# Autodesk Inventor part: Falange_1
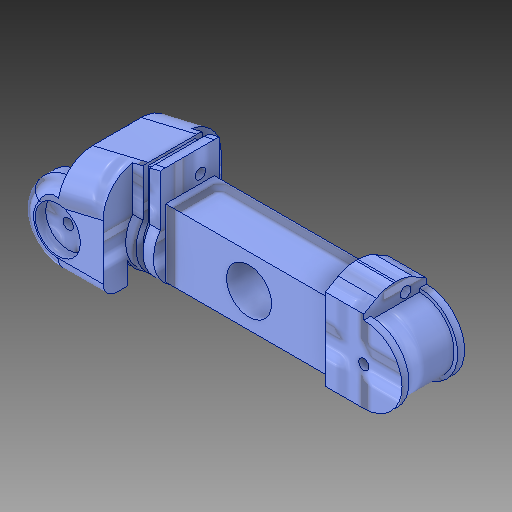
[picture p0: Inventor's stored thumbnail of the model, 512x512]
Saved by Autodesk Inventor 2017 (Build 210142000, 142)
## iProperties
Created: 2017-02
Part Number: Falange_1
Material: Generic
Document SubType Name: Modeling
Designer: alez_
Density: 1 g/cm^3
Appearance: 4in Square - Light Blue
Author: alez_
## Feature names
1. Extrusion1
2. Extrusion2
3. Extrusion3
4. Extrusion4
5. Extrusion5
6. Extrusion6
7. Extrusion7
8. Extrusion8
9. Sweep1
10. Sweep2
11. Fillet1
12. Fillet2
13. Extrusion9
14. Extrusion10
15. Extrusion11
16. Extrusion12
17. Extrusion13
18. Fillet3
19. Fillet4
20. Extrusion14
21. Extrusion16
22. Extrusion17
23. Extrusion18
24. Extrusion19
25. Extrusion20
26. Extrusion21
27. Extrusion22
28. Extrusion23
29. Extrusion24
30. Fillet5
31. Extrusion25
32. Extrusion26
## Parameters: d0 = 18 mm, d1 = 17 mm, d2 = 16 mm, d3 = 0, d4 = 8.5 mm, d6 = 4.25 mm, d7 = 8.5 mm, d8 = 4 mm, d9 = 0, d17 = 17 mm, d18 = 0, d19 = 13.5 mm, d20 = 17 mm, d21 = 0, d22 = 6.5 mm, d23 = 1.5 mm, d24 = 0, d25 = 1.5 mm, d26 = 0, d27 = 1.5 mm, d28 = 14 mm, d29 = 0, d30 = 5 mm, d33 = 8 mm, d34 = 0, d35 = 1.5 mm, d36 = 0, d37 = 0, d38 = 1.5 mm, d39 = 0, d40 = 0, d41 = 5 mm, d42 = 5 mm, d44 = 0, d45 = 11 mm, d47 = 0, d49 = 1 mm, d50 = 1 mm, d51 = 0.75 mm, d52 = 11 mm, d55 = 0, d56 = 10.5 mm, d57 = 1 mm, d58 = 0, d59 = 2 mm, d60 = 0, d61 = 1 mm, d62 = 2 mm, d63 = 15 mm, d64 = 3.25 mm, d65 = 0, d76 = -1.5 mm, d77 = 1 mm, d78 = 1 mm, d79 = 0, d85 = 13.5 mm, d86 = 7 mm, d87 = 35 mm, d88 = 0, d89 = 5.5 mm, d91 = 7 mm, d92 = 0, d93 = 1 mm, d94 = 8 mm, d95 = 0, d96 = 0, d97 = 1.5 mm, d98 = 9 mm, d99 = 0, d100 = 0.5 mm, d101 = 0, d103 = 7 mm, d104 = 0, d105 = 3.25 mm, d106 = 7 mm, d107 = 0, d108 = 0.75 mm, d109 = 3 mm, d110 = 0.75 mm, d111 = 3 mm, d112 = 5.5 mm, d113 = 0, d114 = 5 mm, d115 = 3 mm, d116 = 2 mm, d117 = 1.5 mm, d118 = 40.5 mm, d119 = 0, d120 = 6.5 mm, d122 = 0
